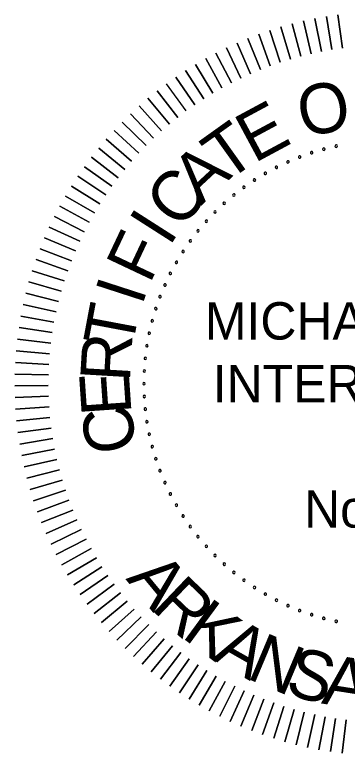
# Model space of a CAD drawing. Extents: x 166 to 3995, y -61 to 2074.
# Drawn here: x 2947.3 to 3062.3, y 407.4 to 662.6 of the extents above; entities that cross this region are included whole.
import ezdxf

# ---------------------------------------------------------------- set-up
doc = ezdxf.new("R2010")
doc.units = 0
doc.layers.add('G-ANNO-TEXT', color=7, linetype='Continuous')

msp = doc.modelspace()

# ---------------------------------------------------------------- linework, layer by layer
at = {"layer": 'G-ANNO-TEXT'}
for points in [[(3053.34, 649.9), (3051.11, 661.28)], [(3051.11, 661.28), (3053.34, 649.9)], [(3056.96, 650.55), (3055.08, 662)], [(3055.08, 662), (3056.96, 650.55)], [(3060.6, 651.09), (3059.08, 662.59)], [(3059.08, 662.59), (3060.6, 651.09)], [(3046.18, 648.25), (3043.23, 659.47)], [(3043.23, 659.47), (3046.18, 648.25)], [(3049.75, 649.13), (3047.15, 660.44)], [(3047.15, 660.44), (3049.75, 649.13)], [(3039.13, 646.16), (3035.48, 657.17)], [(3035.48, 657.17), (3039.13, 646.16)], [(3042.64, 647.26), (3039.34, 658.38)], [(3039.34, 658.38), (3042.64, 647.26)], [(3032.23, 643.63), (3027.9, 654.4)], [(3027.9, 654.4), (3032.23, 643.63)], [(3035.66, 644.95), (3031.67, 655.84)], [(3031.67, 655.84), (3035.66, 644.95)], [(3025.5, 640.68), (3020.5, 651.14)], [(3020.5, 651.14), (3025.5, 640.68)], [(3028.84, 642.21), (3024.17, 652.83)], [(3024.17, 652.83), (3028.84, 642.21)], [(3022.2, 639.04), (3016.88, 649.35)], [(3016.88, 649.35), (3022.2, 639.04)], [(3018.96, 637.3), (3013.32, 647.44)], [(3013.32, 647.44), (3018.96, 637.3)], [(3012.66, 633.53), (3006.39, 643.28)], [(3006.39, 643.28), (3012.66, 633.53)], [(3015.78, 635.46), (3009.82, 645.42)], [(3009.82, 645.42), (3015.78, 635.46)], [(3009.6, 631.49), (3003.02, 641.05)], [(3003.02, 641.05), (3009.6, 631.49)], [(3006.6, 629.36), (2999.73, 638.71)], [(3003.67, 627.14), (2996.51, 636.26)], [(2996.51, 636.26), (3003.67, 627.14)], [(3000.82, 624.82), (2993.37, 633.72)], [(2993.37, 633.72), (3000.82, 624.82)], [(2998.03, 622.42), (2990.32, 631.08)], [(2990.32, 631.08), (2998.03, 622.42)], [(2995.33, 619.93), (2987.34, 628.34)], [(2987.34, 628.34), (2995.33, 619.93)], [(2992.7, 617.36), (2984.46, 625.51)], [(2984.46, 625.51), (2992.7, 617.36)], [(2990.16, 614.7), (2981.66, 622.6)], [(2981.66, 622.6), (2990.16, 614.7)], [(2987.7, 611.97), (2978.96, 619.59)], [(2978.96, 619.59), (2987.7, 611.97)], [(2985.33, 609.16), (2976.35, 616.5)], [(2976.35, 616.5), (2985.33, 609.16)], [(2983.05, 606.28), (2973.84, 613.34)], [(2973.84, 613.34), (2983.05, 606.28)], [(2980.86, 603.33), (2971.43, 610.09)], [(2971.43, 610.09), (2980.86, 603.33)], [(2978.76, 600.31), (2969.13, 606.77)], [(2969.13, 606.77), (2978.76, 600.31)], [(2976.76, 597.22), (2966.93, 603.38)], [(2966.93, 603.38), (2976.76, 597.22)], [(2974.85, 594.08), (2964.84, 599.93)], [(2964.84, 599.93), (2974.85, 594.08)], [(2973.05, 590.88), (2962.86, 596.41)], [(2962.86, 596.41), (2973.05, 590.88)], [(2971.35, 587.62), (2960.98, 592.83)], [(2960.98, 592.83), (2971.35, 587.62)], [(2969.75, 584.31), (2959.23, 589.19)], [(2959.23, 589.19), (2969.75, 584.31)], [(2968.26, 580.95), (2957.58, 585.49)], [(2957.58, 585.49), (2968.26, 580.95)], [(2966.87, 577.54), (2956.06, 581.75)], [(2956.06, 581.75), (2966.87, 577.54)], [(2965.59, 574.1), (2954.65, 577.97)], [(2954.65, 577.97), (2965.59, 574.1)], [(2964.42, 570.61), (2953.36, 574.14)], [(2953.36, 574.14), (2964.42, 570.61)], [(2963.35, 567.09), (2952.2, 570.27)], [(2952.2, 570.27), (2963.35, 567.09)], [(2962.4, 563.54), (2951.15, 566.36)], [(2951.15, 566.36), (2962.4, 563.54)], [(2961.57, 559.96), (2950.23, 562.43)], [(2950.23, 562.43), (2961.57, 559.96)], [(2960.84, 556.36), (2949.43, 558.47)], [(2949.43, 558.47), (2960.84, 556.36)], [(2960.23, 552.73), (2948.76, 554.48)], [(2948.76, 554.48), (2960.23, 552.73)], [(2959.73, 549.09), (2948.22, 550.48)], [(2948.22, 550.48), (2959.73, 549.09)], [(2959.35, 545.43), (2947.79, 546.46)], [(2947.79, 546.46), (2959.35, 545.43)], [(2959.08, 541.77), (2947.5, 542.43)], [(2947.5, 542.43), (2959.08, 541.77)], [(2958.93, 538.1), (2947.33, 538.4)], [(2947.33, 538.4), (2958.93, 538.1)], [(2958.89, 534.42), (2947.29, 534.35)], [(2947.29, 534.35), (2958.89, 534.42)], [(2958.97, 530.74), (2947.38, 530.32)], [(2947.38, 530.32), (2958.97, 530.74)], [(2959.16, 527.07), (2947.59, 526.28)], [(2947.59, 526.28), (2959.16, 527.07)], [(2959.47, 523.41), (2947.93, 522.25)], [(2947.93, 522.25), (2959.47, 523.41)], [(2959.89, 519.76), (2948.4, 518.24)], [(2948.4, 518.24), (2959.89, 519.76)], [(2960.43, 516.12), (2948.99, 514.24)], [(2948.99, 514.24), (2960.43, 516.12)], [(2961.09, 512.5), (2949.7, 510.27)], [(2949.7, 510.27), (2961.09, 512.5)], [(2961.85, 508.91), (2950.55, 506.31)], [(2950.55, 506.31), (2961.85, 508.91)], [(2962.73, 505.34), (2951.51, 502.39)], [(2951.51, 502.39), (2962.73, 505.34)], [(2963.72, 501.8), (2952.6, 498.5)], [(2952.6, 498.5), (2963.72, 501.8)], [(2964.82, 498.29), (2953.81, 494.64)], [(2953.81, 494.64), (2964.82, 498.29)], [(2966.03, 494.82), (2955.14, 490.83)], [(2955.14, 490.83), (2966.03, 494.82)], [(2967.35, 491.39), (2956.59, 487.06)], [(2956.59, 487.06), (2967.35, 491.39)], [(2968.77, 488), (2958.15, 483.33)], [(2958.15, 483.33), (2968.77, 488)], [(2970.31, 484.66), (2959.84, 479.66)], [(2959.84, 479.66), (2970.31, 484.66)], [(2971.94, 481.36), (2961.64, 476.04)], [(2961.64, 476.04), (2971.94, 481.36)], [(2973.68, 478.13), (2963.55, 472.48)], [(2963.55, 472.48), (2973.68, 478.13)], [(2975.52, 474.94), (2965.57, 468.98)], [(2965.57, 468.98), (2975.52, 474.94)], [(2977.46, 471.82), (2967.7, 465.55)], [(2967.7, 465.55), (2977.46, 471.82)], [(2979.49, 468.76), (2969.93, 462.18)], [(2969.93, 462.18), (2979.49, 468.76)], [(2981.62, 465.76), (2972.28, 458.89)], [(2972.28, 458.89), (2981.62, 465.76)], [(2983.85, 462.83), (2974.72, 455.67)], [(2974.72, 455.67), (2983.85, 462.83)], [(2986.16, 459.98), (2977.26, 452.53)], [(2977.26, 452.53), (2986.16, 459.98)], [(2988.56, 457.2), (2979.91, 449.48)], [(2979.91, 449.48), (2988.56, 457.2)], [(2991.05, 454.49), (2982.64, 446.5)], [(2982.64, 446.5), (2991.05, 454.49)], [(2993.63, 451.86), (2985.47, 443.62)], [(2985.47, 443.62), (2993.63, 451.86)], [(2996.28, 449.32), (2988.39, 440.82)], [(2988.39, 440.82), (2996.28, 449.32)], [(2991.39, 438.12), (2999.01, 446.86)], [(2999.01, 446.86), (2991.39, 438.12)], [(2994.48, 435.51), (3001.82, 444.49)], [(3001.82, 444.49), (2994.48, 435.51)], [(2997.65, 433), (3004.7, 442.21)], [(3004.7, 442.21), (2997.65, 433)], [(3000.89, 430.59), (3007.66, 440.02)], [(3007.66, 440.02), (3000.89, 430.59)], [(3004.21, 428.29), (3010.67, 437.92)], [(3010.67, 437.92), (3004.21, 428.29)], [(3007.6, 426.09), (3013.76, 435.92)], [(3013.76, 435.92), (3007.6, 426.09)], [(3011.05, 424), (3016.9, 434.02)], [(3016.9, 434.02), (3011.05, 424)], [(3014.58, 422.02), (3020.11, 432.21)], [(3020.11, 432.21), (3014.58, 422.02)], [(3018.16, 420.15), (3023.37, 430.51)], [(3023.37, 430.51), (3018.16, 420.15)], [(3021.8, 418.39), (3026.68, 428.91)], [(3026.68, 428.91), (3021.8, 418.39)], [(3025.49, 416.75), (3030.03, 427.42)], [(3030.03, 427.42), (3025.49, 416.75)], [(3029.23, 415.22), (3033.44, 426.03)], [(3033.44, 426.03), (3029.23, 415.22)], [(3033.02, 413.81), (3036.89, 424.75)], [(3036.89, 424.75), (3033.02, 413.81)], [(3036.85, 412.53), (3040.37, 423.58)], [(3040.37, 423.58), (3036.85, 412.53)], [(3040.72, 411.36), (3043.89, 422.52)], [(3043.89, 422.52), (3040.72, 411.36)], [(3044.62, 410.31), (3047.44, 421.57)], [(3047.44, 421.57), (3044.62, 410.31)], [(3048.55, 409.39), (3051.02, 420.73)], [(3051.02, 420.73), (3048.55, 409.39)], [(3052.51, 408.6), (3054.62, 420)], [(3054.62, 420), (3052.51, 408.6)], [(3056.5, 407.92), (3058.25, 419.39)], [(3058.25, 419.39), (3056.5, 407.92)], [(3060.5, 407.38), (3061.89, 418.89)], [(3061.89, 418.89), (3060.5, 407.38)]]:
    msp.add_lwpolyline(points, dxfattribs=at)
for centre, start, end in [((3058.46, 617.18), 12, 192), ((3049.97, 614.91), 18, 198), ((3054.18, 616.15), 15, 195), ((3054.18, 616.15), 195, 15), ((3058.46, 617.18), 192, 12), ((3045.83, 613.44), 21, 201), ((3045.83, 613.44), 201, 21), ((3049.97, 614.91), 198, 18), ((3037.8, 609.87), 27, 207), ((3037.8, 609.87), 207, 27), ((3041.77, 611.76), 24, 204), ((3041.77, 611.76), 204, 24), ((3033.94, 607.77), 30, 210), ((3033.94, 607.77), 210, 30), ((3030.19, 605.47), 33, 213), ((3030.19, 605.47), 213, 33), ((3026.57, 602.98), 36, 216), ((3026.57, 602.98), 216, 36), ((3023.08, 600.31), 39, 219), ((3023.08, 600.31), 219, 39), ((3019.74, 597.45), 42, 222), ((3019.74, 597.45), 222, 42), ((3016.55, 594.43), 45, 225), ((3016.55, 594.43), 225, 45), ((3013.53, 591.24), 48, 228), ((3013.53, 591.24), 228, 48), ((3010.67, 587.9), 51, 231), ((3010.67, 587.9), 231, 51), ((3008, 584.41), 54, 234), ((3008, 584.41), 234, 54), ((3005.51, 580.79), 57, 237), ((3005.51, 580.79), 237, 57), ((3003.21, 577.04), 60, 240), ((3003.21, 577.04), 240, 60), ((3001.12, 573.18), 63, 243), ((3001.12, 573.18), 243, 63), ((2999.22, 569.21), 66, 246), ((2999.22, 569.21), 246, 66), ((2997.54, 565.15), 69, 249), ((2997.54, 565.15), 249, 69), ((2996.08, 561.01), 72, 252), ((2996.08, 561.01), 252, 72), ((2994.83, 556.8), 75, 255), ((2994.83, 556.8), 255, 75), ((2993.8, 552.52), 78, 258), ((2993.8, 552.52), 258, 78), ((2993, 548.2), 81, 261), ((2993, 548.2), 261, 81), ((2992.43, 543.85), 84, 264), ((2992.43, 543.85), 264, 84), ((2992.08, 539.46), 87, 267), ((2992.08, 539.46), 267, 87), ((2991.97, 535.07), 90, 270), ((2991.97, 535.07), 270, 90), ((2992.08, 530.68), 93, 273), ((2992.08, 530.68), 273, 93), ((2992.43, 526.3), 96, 276), ((2992.43, 526.3), 276, 96), ((2993, 521.94), 99, 279), ((2993, 521.94), 279, 99), ((2993.8, 517.62), 102, 282), ((2993.8, 517.62), 282, 102), ((2994.83, 513.35), 105, 285), ((2994.83, 513.35), 285, 105), ((2996.08, 509.13), 108, 288), ((2996.08, 509.13), 288, 108), ((2997.54, 504.99), 111, 291), ((2997.54, 504.99), 291, 111), ((2999.22, 500.93), 114, 294), ((2999.22, 500.93), 294, 114), ((3001.12, 496.96), 117, 297), ((3001.12, 496.96), 297, 117), ((3003.21, 493.1), 120, 300), ((3003.21, 493.1), 300, 120), ((3005.51, 489.35), 123, 303), ((3005.51, 489.35), 303, 123), ((3008, 485.73), 126, 306), ((3008, 485.73), 306, 126), ((3010.67, 482.24), 129, 309), ((3010.67, 482.24), 309, 129), ((3013.53, 478.9), 132, 312), ((3013.53, 478.9), 312, 132), ((3016.55, 475.71), 135, 315), ((3016.55, 475.71), 315, 135), ((3019.74, 472.69), 138, 318), ((3019.74, 472.69), 318, 138), ((3023.08, 469.84), 141, 321), ((3023.08, 469.84), 321, 141), ((3026.57, 467.16), 144, 324), ((3026.57, 467.16), 324, 144), ((3030.19, 464.67), 147, 327), ((3030.19, 464.67), 327, 147), ((3033.94, 462.37), 150, 330), ((3033.94, 462.37), 330, 150), ((3037.8, 460.28), 153, 333), ((3037.8, 460.28), 333, 153), ((3041.77, 458.39), 156, 336), ((3041.77, 458.39), 336, 156), ((3045.83, 456.7), 159, 339), ((3045.83, 456.7), 339, 159), ((3049.97, 455.24), 162, 342), ((3049.97, 455.24), 342, 162), ((3054.18, 453.99), 345, 165), ((3054.18, 453.99), 165, 345), ((3058.46, 452.96), 168, 348), ((3058.46, 452.96), 348, 168)]:
    msp.add_arc(centre, 0.431, start, end, dxfattribs=at)

# ---------------------------------------------------------------- texts
for s, rotation, p in [('O', 10.7295, (3046.81, 620.16)), ('E', 28.279, (3030.08, 611.14)), ('T', 35.5725, (3020.46, 604.47)), ('A', 42.8659, (3011.71, 596.51)), ('C', 50.1594, (3004.46, 587.9)), ('I', 57.4529, (3000.72, 582.14)), ('F', 64.7464, (2993.96, 569.26)), ('I', 72.0398, (2991.29, 561.68)), ('T', 79.3333, (2987.87, 546.84)), ('R', 86.6268, (2987.08, 535.45)), ('E', 93.9203, (2987.71, 524.69)), ('C', 101.2137, (2989.92, 512.71)), ('A', 309.5859, (2985.51, 467.61)), ('R', 316.3356, (2994.06, 457.46)), ('K', 323.6428, (3004.6, 447.68)), ('A', 330.3925, (3015.36, 439.9)), ('N', 337.1422, (3026.97, 433.44)), ('S', 344.4494, (3040.29, 428.04)), ('A', 351.1991, (3053.12, 424.6))]:
    msp.add_text(s, height=17.23, rotation=rotation, dxfattribs=at).set_placement(p)
for s, height, p in [('MICHAEL BAKER', 12.9215, (3013.04, 550.34)), (' INTERNATIONAL', 12.9215, (3010.96, 528.62)), (' No. 1126', 12.922, (3042.56, 485.35))]:
    msp.add_text(s, height=height, dxfattribs=at).set_placement(p)

doc.saveas('drawing.dxf')
